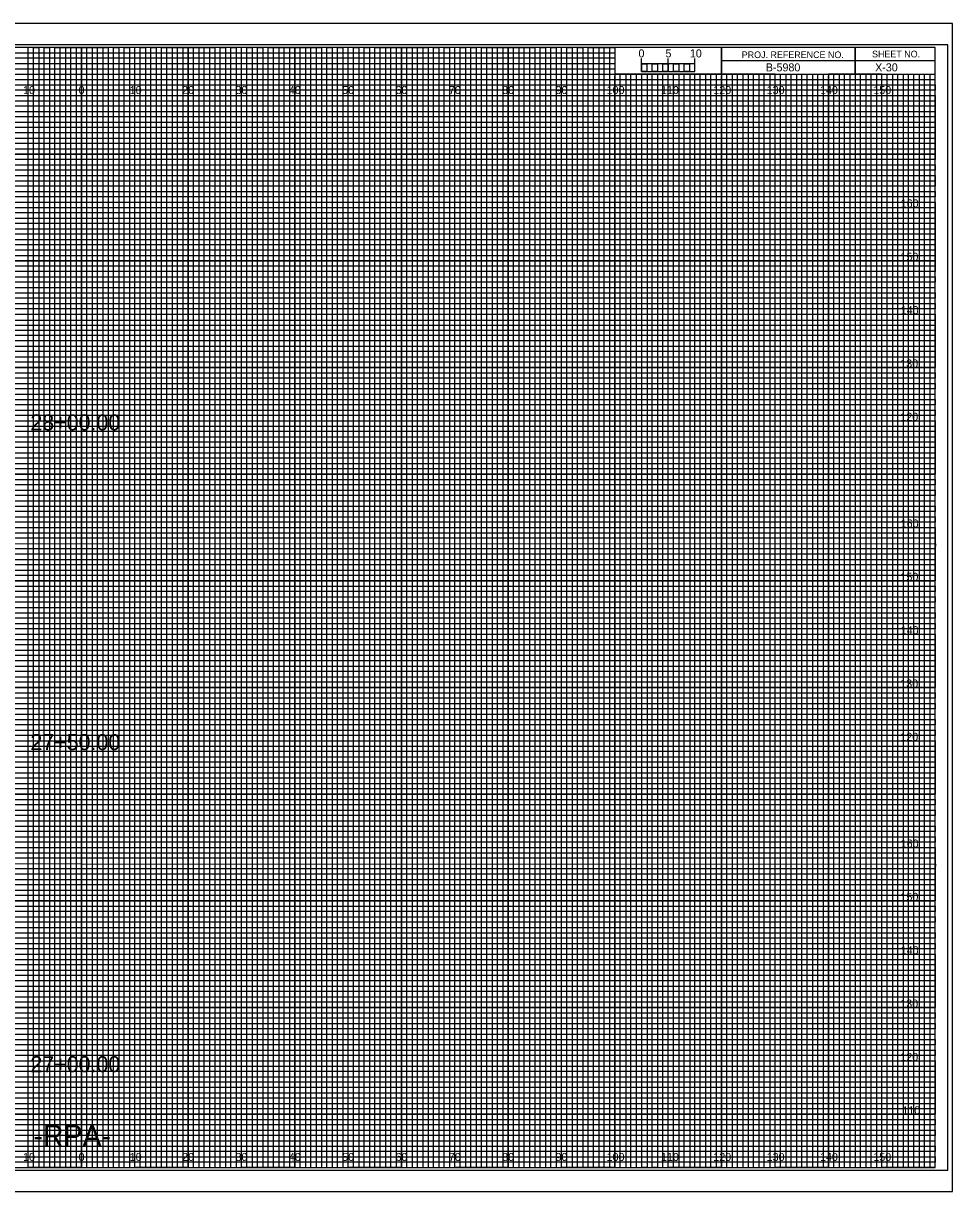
# Model space of a CAD drawing. Extents: x -13 to 323, y -5 to 1974.
# Drawn here: x 149.1 to 323.3, y 1315.5 to 1534.5 of the extents above; entities that cross this region are included whole.
import ezdxf

# ---------------------------------------------------------------- set-up
doc = ezdxf.new("R2010")
doc.units = 0
for name, color, linetype in [('Exist Cross Section Cell', 7, 'Continuous'), ('Exist XS Center Line Elevation Label', 7, 'Continuous'), ('Exist XS Ground Line', 7, 'Continuous'), ('Prop CMT Bridge Girder Bottom Critical Point Inside', 7, 'Continuous'), ('Prop CMT Guardrail Graphics', 7, 'Continuous'), ('Prop CMT Guardrail Widen Shoulder', 7, 'Continuous'), ('Prop CMT Pvmt Course 1', 7, 'Continuous'), ('Prop CMT Pvmt Course 2', 7, 'Continuous'), ('Prop CMT Pvmt Course 3', 7, 'Continuous'), ('Prop CMT Pvmt Surface', 7, 'Continuous'), ('Prop CMT Pvmt Surface Shoulder', 7, 'Continuous'), ('Prop CMT Shld Paved Course 1', 7, 'Continuous'), ('Prop CMT Shld Paved Course 2', 7, 'Continuous'), ('Prop CMT Shld Paved Course 3', 7, 'Continuous'), ('Prop CMT Slope Grass', 7, 'Continuous'), ('Prop CMT Subgrade Earthwork', 7, 'Continuous'), ('Scratch_Level_1', 7, 'Continuous')]:
    doc.layers.add(name, color=color, linetype=linetype)

msp = doc.modelspace()

# ---------------------------------------------------------------- linework, layer by layer
at = {"layer": 'Exist XS Center Line Elevation Label'}
for points in [[(145, 1320), (155, 1320), (155, 1530), (165, 1530), (165, 1320), (175, 1320), (175, 1530), (185, 1530), (185, 1320), (195, 1320), (195, 1530), (205, 1530), (205, 1320), (215, 1320), (215, 1530), (225, 1530), (225, 1320), (235, 1320), (235, 1530), (245, 1530), (245, 1320), (255, 1320), (255, 1530), (259.93, 1530), (260, 1530), (260, 1525), (264.99, 1525), (264.99, 1320), (275, 1320), (275, 1525), (285, 1525), (285, 1320), (295, 1320), (295, 1525), (305, 1525), (305, 1320), (315, 1320), (315, 1525)], [(0, 1525), (275, 1525)], [(0, 1505), (320, 1505), (320, 1515), (0, 1515)], [(0, 1485), (320, 1485), (320, 1495), (0, 1495)], [(0, 1465), (320, 1465), (320, 1475), (0, 1475)], [(0, 1445), (320, 1445), (320, 1455), (0, 1455)], [(0, 1425), (320, 1425), (320, 1435), (0, 1435)], [(0, 1405), (320, 1405), (320, 1415), (0, 1415)], [(0, 1385), (320, 1385), (320, 1395), (0, 1395)], [(0, 1365), (320, 1365), (320, 1375), (0, 1375)], [(0, 1345), (320, 1345), (320, 1355), (0, 1355)], [(0, 1325), (320, 1325), (320, 1335), (0, 1335)]]:
    msp.add_lwpolyline(points, dxfattribs=at)
at = {"layer": 'Exist XS Ground Line'}
for p, q in [((150, 1530), (140, 1530)), ((150, 1320), (150, 1530)), ((170, 1530), (160, 1530)), ((160, 1530), (160, 1320)), ((170, 1320), (170, 1530)), ((190, 1530), (180, 1530)), ((180, 1530), (180, 1320)), ((190, 1320), (190, 1530)), ((210, 1530), (200, 1530)), ((200, 1530), (200, 1320)), ((210, 1320), (210, 1530)), ((230, 1530), (220, 1530)), ((220, 1530), (220, 1320)), ((230, 1320), (230, 1530)), ((250, 1530), (240, 1530)), ((240, 1530), (240, 1320)), ((250, 1320), (250, 1530)), ((260, 1530), (260, 1320)), ((270, 1320), (270, 1525)), ((290, 1525), (280, 1525)), ((280, 1525), (280, 1320)), ((290, 1320), (290, 1525)), ((310, 1525), (300, 1525)), ((300, 1525), (300, 1320)), ((310, 1320), (310, 1525)), ((160, 1320), (150, 1320)), ((180, 1320), (170, 1320)), ((200, 1320), (190, 1320)), ((220, 1320), (210, 1320)), ((240, 1320), (230, 1320)), ((260, 1320), (250, 1320)), ((280, 1320), (270, 1320)), ((300, 1320), (290, 1320)), ((320, 1320), (310, 1320)), ((320, 1320), (320, 1320))]:
    msp.add_line(p, q, dxfattribs=at)
for points in [[(0, 1520), (320, 1520), (320, 1510), (0, 1510)], [(0, 1500), (320, 1500), (320, 1490), (0, 1490)], [(0, 1480), (320, 1480), (320, 1470), (0, 1470)], [(0, 1460), (320, 1460), (320, 1450), (0, 1450)], [(0, 1440), (320, 1440), (320, 1430), (0, 1430)], [(0, 1420), (320, 1420), (320, 1410), (0, 1410)], [(0, 1400), (320, 1400), (320, 1390), (0, 1390)], [(0, 1380), (320, 1380), (320, 1370), (0, 1370)], [(0, 1360), (320, 1360), (320, 1350), (0, 1350)], [(0, 1340), (320, 1340), (320, 1330), (0, 1330)]]:
    msp.add_lwpolyline(points, dxfattribs=at)
at = {"layer": 'Prop CMT Pvmt Course 2'}
for p, q in [((265, 1525.49), (265, 1527.9)), ((265, 1526.9), (265, 1527.9)), ((270, 1525.49), (270, 1527.9)), ((275, 1525.49), (275, 1527.9)), ((275, 1526.9), (275, 1527.9))]:
    msp.add_line(p, q, dxfattribs=at)
for points in [[(275, 1526.9), (265, 1526.9), (265, 1525.49), (275, 1525.49)], [(265, 1526.9), (266, 1526.9), (266, 1525.49), (265, 1525.49)], [(267, 1526.9), (268, 1526.9), (268, 1525.49), (267, 1525.49)], [(269, 1526.9), (270, 1526.9), (270, 1525.49), (269, 1525.49)], [(271, 1526.9), (272, 1526.9), (272, 1525.49), (271, 1525.49)], [(273, 1526.9), (274, 1526.9), (274, 1525.49), (273, 1525.49)]]:
    msp.add_lwpolyline(points, close=True, dxfattribs=at)
at = {"layer": 'Prop CMT Pvmt Course 3'}
msp.add_lwpolyline([(-13.4, 1315.5), (323.3, 1315.5), (323.3, 1534.5), (-13.4, 1534.5)], close=True, dxfattribs=at)
at = {"layer": 'Prop CMT Pvmt Surface'}
for p, q in [((150, 1320), (150, 1530)), ((160, 1320), (160, 1530)), ((170, 1320), (170, 1530)), ((180, 1320), (180, 1530)), ((190, 1320), (190, 1530)), ((200, 1320), (200, 1530)), ((210, 1320), (210, 1530)), ((220, 1320), (220, 1530)), ((230, 1320), (230, 1530)), ((240, 1320), (240, 1530)), ((250, 1320), (250, 1530)), ((260, 1320), (260, 1524.69)), ((270, 1320), (270, 1524.69)), ((280, 1320), (280, 1524.69)), ((290, 1320), (290, 1524.69)), ((300, 1320), (300, 1524.69)), ((310, 1320), (310, 1524.69)), ((0, 1520), (320, 1520)), ((0, 1510), (320, 1510)), ((0, 1500), (320, 1500)), ((0, 1490), (320, 1490)), ((0, 1480), (320, 1480)), ((0, 1470), (320, 1470)), ((0, 1460), (320, 1460)), ((0, 1450), (320, 1450)), ((0, 1440), (320, 1440)), ((0, 1430), (320, 1430)), ((0, 1420), (320, 1420)), ((0, 1410), (320, 1410)), ((0, 1400), (320, 1400)), ((0, 1390), (320, 1390)), ((0, 1380), (320, 1380)), ((0, 1370), (320, 1370)), ((0, 1360), (320, 1360)), ((0, 1350), (320, 1350)), ((0, 1340), (320, 1340)), ((0, 1330), (320, 1330))]:
    msp.add_line(p, q, dxfattribs=at)
at = {"layer": 'Prop CMT Pvmt Surface Shoulder'}
for p, q in [((323.3, 1534.5), (-13.4, 1534.5)), ((-13.4, 1315.5), (323.3, 1315.5))]:
    msp.add_line(p, q, dxfattribs=at)
at = {"layer": 'Prop CMT Shld Paved Course 1'}
for p, q in [((0, 1529), (260, 1529)), ((260, 1529), (260, 1527.98)), ((260, 1527.98), (0, 1527.98)), ((0, 1527), (260, 1527)), ((260, 1527), (260, 1525.89)), ((260, 1525.89), (0, 1525.89)), ((0, 1524), (320, 1524))]:
    msp.add_line(p, q, dxfattribs=at)
for points in [[(0, 1523), (270, 1523), (320, 1523), (320, 1522), (0, 1522)], [(0, 1521), (320, 1521), (320, 1519), (0, 1519)], [(0, 1518), (320, 1518), (320, 1517), (0, 1516.98)], [(0, 1516), (320, 1516), (320, 1514), (0, 1514)], [(0, 1513), (320, 1513), (320, 1512), (0, 1512)], [(0, 1511), (320, 1511), (320, 1509), (0, 1509)], [(0, 1508), (320, 1508), (320, 1507), (0, 1507)], [(0, 1506), (320, 1506), (320, 1504), (0, 1504)], [(0, 1503), (320, 1503), (320, 1502), (0, 1502)], [(0, 1501), (320, 1501), (320, 1499), (0, 1499)], [(0, 1498), (320, 1498), (320, 1497), (0, 1497)], [(0, 1496), (320, 1496), (320, 1493.95), (320, 1493), (320, 1492), (0, 1492)], [(0, 1494), (320, 1494), (320, 1493), (0, 1493)], [(0, 1491), (320, 1491), (320, 1489), (0, 1489.03)], [(0, 1489.03), (320, 1489), (320, 1488), (0, 1488)], [(0, 1487), (320, 1487), (320, 1486), (0, 1486)], [(0, 1484), (320, 1484), (320, 1483), (0, 1483)], [(0, 1482), (320, 1482), (320, 1481), (0, 1481)], [(-0.07, 1478.89), (320, 1478.89), (320, 1477.88), (-0.07, 1477.88)], [(0, 1477), (320, 1477), (320, 1476), (0, 1476)], [(0, 1474), (320, 1474), (320, 1473), (0, 1473)], [(0, 1472), (320, 1472), (320, 1471), (0, 1471)], [(0, 1469), (320, 1469), (320, 1468), (0, 1468)], [(0, 1467), (320, 1467), (320, 1466), (0, 1466)], [(0, 1464), (320, 1464), (320, 1463), (0, 1463)], [(0, 1462), (320, 1462), (320, 1461), (0, 1461)], [(0, 1459), (320, 1459), (319.99, 1457.98), (0, 1458)], [(0, 1457), (320, 1457), (320, 1456), (0, 1456)], [(0, 1454), (320, 1454), (320, 1453), (0, 1453)], [(0, 1452), (320, 1452), (320, 1451), (0, 1451)], [(0, 1449), (320, 1449), (320, 1448), (0, 1448)], [(0, 1447), (320, 1447), (320, 1446), (0, 1446)], [(0, 1444), (320, 1444), (320, 1443), (0, 1443)], [(0, 1442), (320, 1442), (320, 1441), (0, 1441)], [(0, 1439), (320, 1439), (320, 1438), (0, 1438)], [(0, 1436.99), (320.07, 1436.91), (320, 1436), (0, 1436)], [(0, 1434), (320, 1434), (320, 1433), (0, 1433)], [(0, 1432), (320, 1432), (320, 1431), (0, 1431)], [(0, 1429), (320, 1429), (320, 1428), (0, 1428)], [(0, 1427), (320, 1427), (320, 1426), (0, 1426)], [(0, 1424), (320, 1424), (320, 1423), (0, 1423)], [(0, 1422), (320, 1422), (320, 1421), (0, 1421)], [(0, 1419), (320, 1419), (320, 1418), (0, 1418)], [(0, 1417), (320, 1417), (320, 1416), (0, 1416)], [(0, 1414), (320, 1414), (320, 1413), (0, 1413)], [(0, 1412), (320, 1412), (320, 1411), (0, 1411)], [(0, 1409), (320, 1409), (320, 1408), (0, 1408)], [(0, 1407), (320, 1407), (320, 1406), (0, 1406)], [(0, 1404), (320, 1404), (320, 1403), (0, 1403)], [(0, 1402), (320, 1402), (320, 1401), (0, 1401)], [(0, 1399), (320, 1399), (319.99, 1397.98), (0, 1398)], [(0, 1397), (320, 1397), (320, 1396), (0, 1396)], [(0, 1394), (320, 1394), (320, 1393), (0, 1393)], [(0, 1392), (320, 1392), (320, 1391), (0, 1391)], [(0, 1389), (320, 1389), (320, 1388), (0, 1388)], [(0, 1387), (320, 1387), (320, 1386), (0, 1386)], [(0, 1384), (320, 1384), (320, 1383), (0, 1383)], [(0, 1382), (320, 1382), (320, 1381), (0, 1381)], [(0, 1379), (320, 1379), (320, 1378), (0, 1378)], [(0, 1376.99), (320.07, 1376.91), (320, 1376), (0, 1376)], [(0, 1374), (320, 1374), (320, 1373), (0, 1373)], [(0, 1372), (320, 1372), (320, 1371), (0, 1371)], [(0, 1369), (320, 1369), (320, 1368), (0, 1368)], [(0, 1367), (320, 1367), (320, 1366), (0, 1366)], [(0, 1364), (320, 1364), (320, 1363), (0, 1363)], [(0, 1362), (320, 1362), (320, 1361), (0, 1361)], [(0, 1359), (320, 1359), (320, 1358), (0, 1358)], [(0, 1357), (320, 1357), (320, 1356), (0, 1356)], [(0, 1354), (320, 1354), (320, 1353), (0, 1353)], [(0, 1352), (320, 1352), (320, 1351), (0, 1351)], [(0, 1349), (320, 1349), (320, 1348), (0, 1348)], [(0, 1347), (320, 1347), (320, 1346), (0, 1346)], [(0, 1344), (320, 1344), (320, 1343), (0, 1343)], [(0, 1342), (320, 1342), (320, 1341), (0, 1341)], [(0, 1339), (320, 1339), (320, 1338), (0, 1338)], [(0, 1337), (320, 1337), (320, 1336), (0, 1336)], [(0, 1334), (320, 1334), (320, 1333), (0, 1333)], [(0, 1332), (320, 1332), (320, 1331), (0, 1331)], [(0, 1329), (320, 1329), (320, 1328), (0, 1328)], [(0, 1327), (320, 1327), (320, 1326), (0, 1326)], [(0, 1324), (320, 1324), (320, 1323), (0, 1323)], [(0, 1322), (320, 1322), (320, 1321), (0, 1321)]]:
    msp.add_lwpolyline(points, dxfattribs=at)
at = {"layer": 'Prop CMT Shld Paved Course 2'}
for p, q in [((305, 1530), (305, 1525)), ((305, 1525), (305, 1530)), ((280, 1527.5), (280, 1525)), ((320, 1527.49), (280, 1527.49)), ((280, 1525), (320, 1525))]:
    msp.add_line(p, q, dxfattribs=at)
for points in [[(320, 1530), (0, 1530), (0, 1320), (320, 1320)], [(280, 1530), (260, 1530), (260, 1525.03), (280, 1525.03)], [(320, 1530), (280, 1530), (280, 1525), (320, 1525)]]:
    msp.add_lwpolyline(points, close=True, dxfattribs=at)
at = {"layer": 'Prop CMT Shld Paved Course 3'}
for p, q in [((267, 1525), (266.01, 1525)), ((266.01, 1525), (266.01, 1320)), ((267, 1320), (267, 1525)), ((269, 1525), (268, 1525)), ((268, 1525), (268, 1320)), ((269, 1320), (269, 1525)), ((266.01, 1320), (265, 1320)), ((268, 1320), (267, 1320))]:
    msp.add_line(p, q, dxfattribs=at)
for points in [[(150, 1320), (151, 1320), (151, 1530), (152, 1530), (152, 1320)], [(152, 1320), (153, 1320), (153, 1530), (154, 1530), (154, 1320)], [(155, 1320), (156, 1320), (156, 1530), (157, 1530), (157, 1320)], [(157, 1320), (158, 1320), (158, 1530), (159, 1530), (159, 1320)], [(160, 1320), (161, 1320), (161, 1530), (162, 1530), (162, 1320)], [(162, 1320), (163, 1320), (163, 1530), (164, 1530), (164, 1320)], [(165, 1320), (166, 1320), (166, 1530), (167, 1530), (167, 1320)], [(167, 1320), (168, 1320), (168, 1530), (169, 1530), (169, 1320)], [(170, 1320), (171, 1320), (171, 1530), (172, 1530), (172, 1320)], [(172, 1320), (173, 1320), (173, 1530), (174, 1530), (174, 1320)], [(175, 1320), (176, 1320), (176, 1530), (177, 1530), (177, 1320)], [(177, 1320), (178, 1320), (178, 1530), (179, 1530), (179, 1320)], [(180, 1320), (181, 1320), (181, 1530), (182, 1530), (182, 1320)], [(182, 1320), (183, 1320), (183, 1530), (184, 1530), (184, 1320)], [(185, 1320), (186, 1320), (186, 1530), (187, 1530), (187, 1320)], [(187, 1320), (188, 1320), (188, 1530), (189, 1530), (189, 1320)], [(190, 1320), (191, 1320), (191, 1530), (192, 1530), (192, 1320)], [(192, 1320), (193, 1320), (193, 1530), (194, 1530), (194, 1320)], [(195, 1320), (196, 1320), (196, 1530), (197, 1530), (197, 1320)], [(197, 1320), (198, 1320), (198, 1530), (199, 1530), (199, 1320)], [(200, 1320), (201, 1320), (201, 1530), (202, 1530), (202, 1320)], [(202, 1320), (203, 1320), (203, 1530), (204, 1530), (204, 1320)], [(205, 1320), (206, 1320), (206, 1530), (207, 1530), (207, 1320)], [(207, 1320), (208, 1320), (208, 1530), (209, 1530), (209, 1320)], [(210, 1320), (211, 1320), (211, 1530), (212, 1530), (212, 1320)], [(212, 1320), (213, 1320), (213, 1530), (214, 1530), (214, 1320)], [(215, 1320), (216, 1320), (216, 1530), (217, 1530), (217, 1320)], [(217, 1320), (218, 1320), (218, 1530), (219, 1530), (219, 1320)], [(220, 1320), (221, 1320), (221, 1530), (222, 1530), (222, 1320)], [(222, 1320), (223, 1320), (223, 1530), (224, 1530), (224, 1320)], [(225, 1320), (226, 1320), (226, 1530), (227, 1530), (227, 1320)], [(227, 1320), (228, 1320), (228, 1530), (229, 1530), (229, 1320)], [(230, 1320), (231, 1320), (231, 1530), (232, 1530), (232, 1320)], [(232, 1320), (233, 1320), (233, 1530), (234, 1530), (234, 1320)], [(235, 1320), (236, 1320), (236, 1530), (237, 1530), (237, 1320)], [(237, 1320), (238, 1320), (238, 1530), (239, 1530), (239, 1320)], [(240, 1320), (241, 1320), (241, 1530), (242, 1530), (242, 1320)], [(242, 1320), (243, 1320), (243, 1530), (244, 1530), (244, 1320)], [(245, 1320), (246, 1320), (246, 1530), (247, 1530), (247, 1320)], [(247, 1320), (248, 1320), (248, 1530), (249, 1530), (249, 1320)], [(250, 1320), (251, 1320), (251, 1530), (252, 1530), (252, 1320)], [(252, 1320), (253, 1320), (253, 1530), (254, 1530), (254, 1320)], [(255, 1320), (256, 1320), (256, 1530), (257, 1530), (257, 1320)], [(257, 1320), (258, 1320), (258, 1530), (259, 1530), (259, 1320)], [(260, 1320), (261, 1320), (261, 1525), (262.02, 1525), (262.02, 1320)], [(262, 1320), (263, 1320), (263, 1525), (263.99, 1525), (263.99, 1320)], [(270, 1320), (270.98, 1320), (270.98, 1525), (272, 1525), (272, 1320)], [(272, 1320), (273, 1320), (273, 1525), (274.05, 1525), (274.05, 1320)], [(275, 1320), (276, 1320), (276, 1525), (277, 1525), (277, 1320)], [(277, 1320), (278, 1320), (278, 1525), (279, 1525), (279, 1320)], [(280, 1320), (281, 1320), (281, 1525), (282, 1525), (282, 1320)], [(282, 1320), (283, 1320), (283, 1525), (284, 1525), (284, 1320)], [(285, 1320), (286, 1320), (286, 1525), (287, 1525), (287, 1320)], [(287, 1320), (288, 1320), (288, 1525), (289, 1525), (289, 1320)], [(290, 1320), (291, 1320), (291, 1525), (292, 1525), (292, 1320)], [(292, 1320), (293, 1320), (293, 1525), (294, 1525), (294, 1320)], [(295, 1320), (296, 1320), (296, 1525), (297, 1525), (297, 1320)], [(297, 1320), (298, 1320), (298, 1525), (299, 1525), (299, 1320)], [(300, 1320), (301, 1320), (301, 1525), (302, 1525), (302, 1320)], [(302, 1320), (303, 1320), (303, 1525), (304, 1525), (304, 1320)], [(305, 1320), (306, 1320), (306, 1525), (307, 1525), (307, 1320)], [(307, 1320), (308, 1320), (308, 1525), (309, 1525), (309, 1320)], [(310, 1320), (311, 1320), (311, 1525), (312, 1525), (312, 1320)], [(312, 1320), (313, 1320), (313, 1525), (314, 1525), (314, 1320)], [(315, 1320), (316, 1320), (316, 1525), (317, 1525), (317, 1320)], [(317, 1320), (318, 1320), (318, 1525), (319, 1525), (319, 1320)]]:
    msp.add_lwpolyline(points, dxfattribs=at)
at = {"layer": 'Prop CMT Subgrade Earthwork'}
msp.add_lwpolyline([(-10.8, 1319.5), (322.4, 1319.5), (322.4, 1530.5), (-10.8, 1530.5)], close=True, dxfattribs=at)

# ---------------------------------------------------------------- texts
at = {"layer": 'Exist Cross Section Cell'}
for s, p in [('10', (149.04, 1521.25)), ('0', (159.45, 1521.25)), ('0', (159.45, 1521.25)), ('10', (169.04, 1521.25)), ('20', (178.86, 1521.25)), ('30', (188.86, 1521.25)), ('40', (198.86, 1521.25)), ('50', (208.86, 1521.25)), ('60', (218.86, 1521.25)), ('70', (228.86, 1521.25)), ('80', (238.86, 1521.25)), ('90', (248.86, 1521.25)), ('100', (258.44, 1521.25)), ('110', (268.62, 1521.25)), ('120', (278.44, 1521.25)), ('130', (288.44, 1521.25)), ('140', (298.44, 1521.25)), ('150', (308.44, 1521.25)), ('10', (149.04, 1321.25)), ('0', (159.45, 1321.25)), ('0', (159.45, 1321.25)), ('10', (169.04, 1321.25)), ('20', (178.86, 1321.25)), ('30', (188.86, 1321.25)), ('40', (198.86, 1321.25)), ('50', (208.86, 1321.25)), ('60', (218.86, 1321.25)), ('70', (228.86, 1321.25)), ('80', (238.86, 1321.25)), ('90', (248.86, 1321.25)), ('100', (258.44, 1321.25)), ('110', (268.62, 1321.25)), ('120', (278.44, 1321.25)), ('130', (288.44, 1321.25)), ('140', (298.44, 1321.25)), ('150', (308.44, 1321.25))]:
    msp.add_text(s, height=1.5, dxfattribs=at).set_placement(p)
at = {"layer": 'Prop CMT Bridge Girder Bottom Critical Point Inside'}
for s, p in [('5', (269.47, 1528.12)), ('10', (274.04, 1528.12))]:
    msp.add_text(s, height=1.5, dxfattribs=at).set_placement(p)
at = {"layer": 'Prop CMT Guardrail Graphics'}
msp.add_text('B-5980', height=1.5, dxfattribs=at).set_placement((288.28, 1525.5))
at = {"layer": 'Prop CMT Guardrail Widen Shoulder'}
msp.add_text('X-30', height=1.5, dxfattribs=at).set_placement((308.77, 1525.5))
at = {"layer": 'Prop CMT Pvmt Course 1'}
for s, p in [('160', (313.57, 1500)), ('150', (313.52, 1490)), ('140', (313.57, 1480)), ('130', (313.49, 1470)), ('120', (313.5, 1460)), ('160', (313.57, 1440)), ('150', (313.52, 1430)), ('140', (313.57, 1420)), ('130', (313.49, 1410)), ('120', (313.5, 1400)), ('160', (313.57, 1380)), ('150', (313.52, 1370)), ('140', (313.57, 1360)), ('130', (313.49, 1350)), ('120', (313.5, 1340)), ('110', (313.88, 1330))]:
    msp.add_text(s, height=1.5, dxfattribs=at).set_placement(p)
at = {"layer": 'Prop CMT Pvmt Course 2'}
msp.add_text('0', height=1.5, dxfattribs=at).set_placement((264.41, 1528.12))
at = {"layer": 'Prop CMT Shld Paved Course 2'}
for s, p in [('PROJ. REFERENCE NO.', (283.77, 1527.99)), ('SHEET NO.', (308.19, 1528.12))]:
    msp.add_text(s, height=1.25, dxfattribs=at).set_placement(p)
at = {"layer": 'Prop CMT Slope Grass'}
for s, p in [('28+00.00', (150.41, 1458.2)), ('27+50.00', (150.41, 1398.27)), ('27+00.00', (150.41, 1337.89))]:
    msp.add_text(s, height=3, dxfattribs=at).set_placement(p)
at = {"layer": 'Scratch_Level_1'}
msp.add_text('-RPA-', height=4, dxfattribs=at).set_placement((150.97, 1324))

doc.saveas('drawing.dxf')
